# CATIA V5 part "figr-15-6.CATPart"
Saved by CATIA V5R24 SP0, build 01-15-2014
Part number: Part1
Bounding box of the stored display mesh (mm): x -50 to 50, y -32.5 to 33.5, z -52 to 1
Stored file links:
  D:\KAVITA\CATIA V5-6R2014 Project_ Kavita\CATIA V5-6R2014_partfiles\Partfiles\c15_catia_v5-6r2014_prt\figr-15-6.CATPart
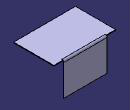
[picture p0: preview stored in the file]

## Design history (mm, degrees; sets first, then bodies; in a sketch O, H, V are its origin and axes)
SheetMetalParameters1: Thickness 1, BendRadius 2, KFactor 0.400515 {= log(min(100,max(20*SheetMetalParameters1.BendRadius,SheetMetalParameters1.Thickness)/SheetMetalParameters1.Thickness))/log(100)/2}, ReliefRadialLength 1, ReliefAxialLength 2, MinimumBendRadius 0
Body1 (main body)
  Sketch1 on xy-plane, origin (0, 0, 0), H (1, 0, 0), V (0, 1, 0)
    line L1 (-50, 32.5) -> (50, 32.5)
    line L2 (50, 32.5) -> (50, -32.5)
    line L3 (50, -32.5) -> (-50, -32.5)
    line L4 (-50, -32.5) -> (-50, 32.5)
    length L1 = 100
    length L2 = 65
    horizontal: L1 H, L3 H
    vertical: L2 V, L4 V
    symmetry: L4 L2 V, L1 L3 H
  Wall1: Thickness 1, Profile Sketch1
  d_NewWallOnEdge1: NewWallOnEdge_Edge edge [face of Wall1 | face of Wall1], KFacteur 0.400515 {= log(min(100,max(20*d_NewWallOnEdge1.Radius,SheetMetalParameters1.Thickness)/SheetMetalParameters1.Thickness))/log(100)/2}, NewWallOnEdge_Length 53, NewWallOnEdge_HeightLimitOffset 0, NewWallOnEdge_WidthOffset1 -15, NewWallOnEdge_WidthOffset2 -15, NewWallOnEdge_Angle 90, NewWallOnEdge_BendRadiusValue 2 {= SheetMetalParameters1.BendRadius}, NewWallOnEdge_BendTable SheetMetalParameters1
